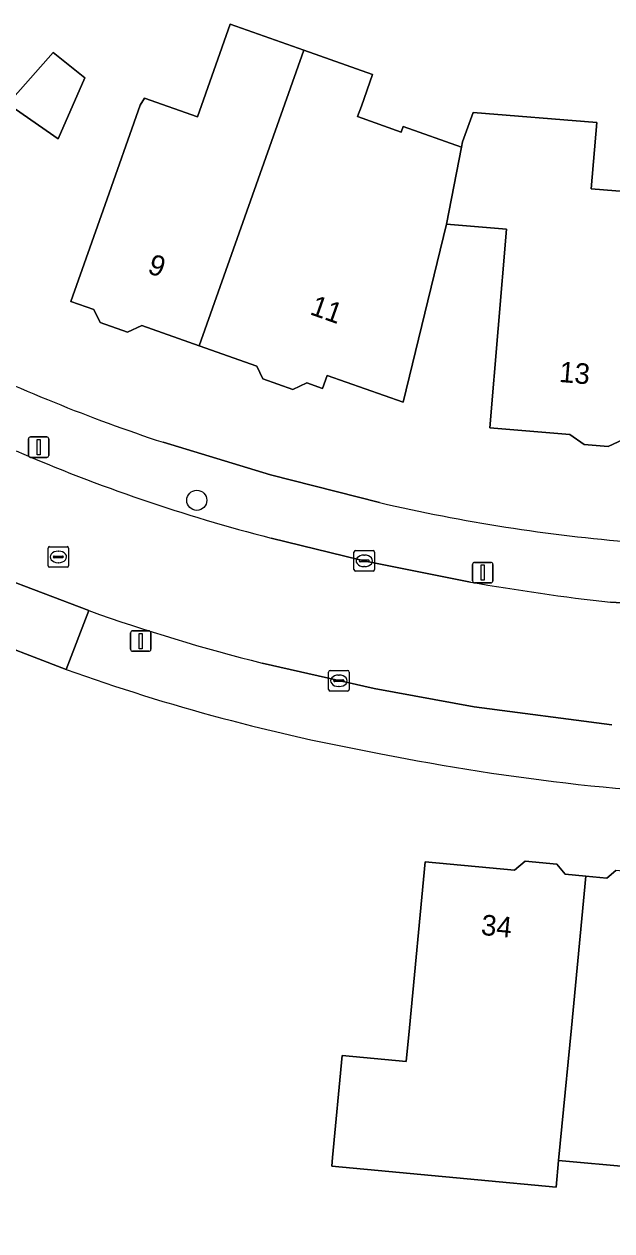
# Model space of a CAD drawing. Extents: x 161347 to 161881, y 382161 to 382804.
# Drawn here: x 161534.1 to 161562.7, y 382240.1 to 382298.9 of the extents above; entities that cross this region are included whole.
import ezdxf

# ---------------------------------------------------------------- set-up
doc = ezdxf.new("R2010")
doc.units = 0
for name, color, linetype in [('IMGEO_Boom', 7, 'Continuous'), ('IMGEO_Erf', 7, 'Continuous'), ('IMGEO_Kolk', 7, 'Continuous'), ('IMGEO_Lichtmast', 7, 'Continuous'), ('IMGEO_Pand', 7, 'Continuous'), ('IMGEO_Pand_nummerreeks', 7, 'Continuous'), ('IMGEO_Rijbaan_lokaal_open', 7, 'Continuous'), ('IMGEO_Rioolput', 7, 'Continuous'), ('IMGEO_Voetpad_open', 7, 'Continuous')]:
    doc.layers.add(name, color=color, linetype=linetype)

msp = doc.modelspace()

# ---------------------------------------------------------------- linework, layer by layer
at = {"layer": 'IMGEO_Boom'}
msp.add_circle((161542.46, 382275.697), 0.489, dxfattribs=at)
at = {"layer": 'IMGEO_Erf'}
for points in [[(161563.214, 382278.661), (161562.476, 382278.312), (161561.319, 382278.408), (161560.611, 382278.898), (161556.721, 382279.219), (161557.53, 382288.906), (161554.609, 382289.153), (161552.505, 382280.471), (161548.799, 382281.783), (161548.572, 382281.142), (161547.811, 382281.412), (161547.14, 382281.092), (161545.678, 382281.61), (161545.38, 382282.234), (161542.582, 382283.225), (161539.787, 382284.215), (161539.082, 382283.879), (161537.751, 382284.351), (161537.45, 382284.984), (161536.323, 382285.383), (161537.993, 382290.096), (161539.711, 382294.946), (161539.91, 382295.288), (161542.49, 382294.374), (161544.089, 382298.888), (161547.675, 382297.617), (161551.015, 382296.434), (161550.47, 382294.897), (161550.288, 382294.382), (161552.401, 382293.633), (161552.498, 382293.908), (161555.344, 382292.899), (161555.394, 382293.152), (161555.904, 382294.591), (161561.924, 382294.094), (161561.658, 382290.87), (161565.47, 382290.555)], [(161540.817, 382278.523), (161546.054, 382276.944), (161551.353, 382275.587)], [(161536.103, 382267.455), (161531.625, 382269.181), (161528.526, 382270.477)], [(161563.653, 382243.214), (161560.073, 382243.551), (161559.947, 382242.238), (161556.14, 382242.596), (161549.029, 382243.265), (161549.069, 382243.686), (161549.536, 382248.664), (161552.653, 382248.371), (161552.806, 382250), (161553.568, 382258.088), (161557.917, 382257.679), (161558.448, 382258.118), (161559.985, 382257.973), (161560.382, 382257.493), (161561.398, 382257.398), (161562.417, 382257.302), (161562.857, 382257.666)]]:
    msp.add_lwpolyline(points, dxfattribs=at)
msp.add_lwpolyline([(161535.705, 382293.299), (161533.261, 382295.006), (161535.469, 382297.513), (161537.017, 382296.273)], close=True, dxfattribs=at)
for centre, radius, start, end in [((161567.389, 382359.053), 84.801, 244.1027, 251.73863), ((161570.871, 382359.893), 86.536, 256.96475, 265.25243), ((161568.859, 382359.195), 97.413, 250.35082, 259.68483), ((161573.13, 382371.474), 110.276, 258.64383, 268.75651)]:
    msp.add_arc(centre, radius, start, end, dxfattribs=at)
at = {"layer": 'IMGEO_Kolk'}
for p, q in [((161550.11, 382272.324), (161550.11, 382273.176)), ((161550.185, 382273.25), (161551.037, 382273.25)), ((161551.111, 382273.176), (161551.111, 382272.324)), ((161550.369, 382272.744), (161550.369, 382272.756)), ((161550.807, 382272.707), (161550.409, 382272.707)), ((161550.412, 382272.793), (161550.81, 382272.793)), ((161550.621, 382272.47), (161550.596, 382272.47)), ((161550.598, 382273.03), (161550.623, 382273.03)), ((161550.853, 382272.756), (161550.853, 382272.744)), ((161551.037, 382272.25), (161550.185, 382272.25)), ((161548.875, 382266.482), (161548.875, 382267.334)), ((161548.95, 382267.408), (161549.802, 382267.408)), ((161549.363, 382267.188), (161549.388, 382267.188)), ((161549.876, 382267.334), (161549.876, 382266.482)), ((161549.134, 382266.902), (161549.134, 382266.914)), ((161549.572, 382266.865), (161549.174, 382266.865)), ((161549.177, 382266.951), (161549.575, 382266.951)), ((161549.386, 382266.628), (161549.361, 382266.628)), ((161549.618, 382266.914), (161549.618, 382266.902)), ((161549.802, 382266.408), (161548.95, 382266.408))]:
    msp.add_line(p, q, dxfattribs=at)
for points in [[(161550.11, 382272.324), (161550.11, 382273.176)], [(161550.185, 382273.25), (161551.037, 382273.25)], [(161551.111, 382273.176), (161551.111, 382272.324)], [(161551.037, 382272.25), (161550.185, 382272.25)], [(161548.875, 382266.482), (161548.875, 382267.334)], [(161548.95, 382267.408), (161549.802, 382267.408)], [(161549.876, 382267.334), (161549.876, 382266.482)], [(161549.802, 382266.408), (161548.95, 382266.408)]]:
    msp.add_lwpolyline(points, dxfattribs=at)
for centre, radius, start, end in [((161550.187, 382273.174), 0.0765, 91.55205, 178.44795), ((161550.187, 382273.174), 0.0765, 91.55205, 178.44795), ((161551.035, 382273.174), 0.0765, 1.55205, 88.44795), ((161551.035, 382273.174), 0.0765, 1.55205, 88.44795), ((161550.409, 382272.753), 0.0403, 85.87752, 175.75265), ((161550.406, 382272.743), 0.0366, 178.93798, 274.71019), ((161550.81, 382272.75), 0.043, 264.86636, 352.45326), ((161550.814, 382272.755), 0.0386, 1.73085, 96.63898), ((161550.187, 382272.326), 0.0765, 181.55205, 268.44795), ((161550.187, 382272.326), 0.0765, 181.55205, 268.44795), ((161551.035, 382272.326), 0.0765, 271.55205, 358.44795), ((161551.035, 382272.326), 0.0765, 271.55205, 358.44795), ((161548.952, 382267.332), 0.0765, 91.55205, 178.44795), ((161548.952, 382267.332), 0.0765, 91.55205, 178.44795), ((161549.8, 382267.332), 0.0765, 1.55205, 88.44795), ((161549.8, 382267.332), 0.0765, 1.55205, 88.44795), ((161549.174, 382266.911), 0.0403, 85.87752, 175.75265), ((161549.171, 382266.901), 0.0366, 178.93798, 274.71019), ((161549.575, 382266.908), 0.043, 264.86636, 352.45326), ((161549.579, 382266.913), 0.0386, 1.73085, 96.63898), ((161548.952, 382266.484), 0.0765, 181.55205, 268.44795), ((161548.952, 382266.484), 0.0765, 181.55205, 268.44795), ((161549.8, 382266.484), 0.0765, 271.55205, 358.44795), ((161549.8, 382266.484), 0.0765, 271.55205, 358.44795)]:
    msp.add_arc(centre, radius, start, end, dxfattribs=at)
for centre, major_axis, ratio, start_param, end_param in [((161550.597, 382272.75), (-0.387, 0.002), 0.722429, 4.712389, 7.853982), ((161550.622, 382272.75), (-0.39, 0.002), 0.717154, 1.570796, 4.712389), ((161549.362, 382266.908), (-0.387, 0.002), 0.722429, 4.712389, 7.853982), ((161549.387, 382266.908), (-0.39, 0.002), 0.717154, 1.570796, 4.712389)]:
    msp.add_ellipse(centre, major_axis=major_axis, ratio=ratio, start_param=start_param, end_param=end_param, dxfattribs=at)
at = {"layer": 'IMGEO_Lichtmast'}
for p, q in [((161534.266, 382277.885), (161534.266, 382278.685)), ((161534.266, 382278.685), (161534.266, 382277.885)), ((161534.366, 382278.785), (161535.156, 382278.785)), ((161535.156, 382278.785), (161534.366, 382278.785)), ((161535.256, 382278.685), (161535.256, 382277.885)), ((161535.256, 382277.885), (161535.256, 382278.685)), ((161535.156, 382277.785), (161534.366, 382277.785)), ((161534.366, 382277.785), (161535.156, 382277.785)), ((161555.88, 382271.776), (161555.88, 382272.576)), ((161555.88, 382272.576), (161555.88, 382271.776)), ((161555.98, 382272.676), (161556.77, 382272.676)), ((161556.77, 382272.676), (161555.98, 382272.676)), ((161556.87, 382272.576), (161556.87, 382271.776)), ((161556.87, 382271.776), (161556.87, 382272.576)), ((161556.77, 382271.676), (161555.98, 382271.676)), ((161555.98, 382271.676), (161556.77, 382271.676)), ((161539.236, 382268.443), (161539.236, 382269.243)), ((161539.236, 382269.243), (161539.236, 382268.443)), ((161539.336, 382269.343), (161540.126, 382269.343)), ((161540.126, 382269.343), (161539.336, 382269.343)), ((161540.226, 382269.243), (161540.226, 382268.443)), ((161540.226, 382268.443), (161540.226, 382269.243)), ((161540.126, 382268.343), (161539.336, 382268.343)), ((161539.336, 382268.343), (161540.126, 382268.343))]:
    msp.add_line(p, q, dxfattribs=at)
for points in [[(161534.686, 382278.66), (161534.836, 382278.66), (161534.836, 382277.91), (161534.686, 382277.91), (161534.686, 382278.66)], [(161556.3, 382272.551), (161556.45, 382272.551), (161556.45, 382271.801), (161556.3, 382271.801), (161556.3, 382272.551)], [(161539.656, 382269.218), (161539.806, 382269.218), (161539.806, 382268.468), (161539.656, 382268.468), (161539.656, 382269.218)]]:
    msp.add_lwpolyline(points, dxfattribs=at)
for centre, start, end in [((161534.366, 382278.685), 90, 180), ((161534.366, 382278.685), 90, 180), ((161535.156, 382278.685), 0, 90), ((161535.156, 382278.685), 360, 90), ((161534.366, 382277.885), 180, 270), ((161534.366, 382277.885), 180, 270), ((161535.156, 382277.885), 270, 0), ((161535.156, 382277.885), 270, 0), ((161555.98, 382272.576), 90, 180), ((161555.98, 382272.576), 90, 180), ((161556.77, 382272.576), 0, 90), ((161556.77, 382272.576), 360, 90), ((161555.98, 382271.776), 180, 270), ((161555.98, 382271.776), 180, 270), ((161556.77, 382271.776), 270, 0), ((161556.77, 382271.776), 270, 0), ((161539.336, 382269.243), 90, 180), ((161539.336, 382269.243), 90, 180), ((161540.126, 382269.243), 0, 90), ((161540.126, 382269.243), 360, 90), ((161539.336, 382268.443), 180, 270), ((161539.336, 382268.443), 180, 270), ((161540.126, 382268.443), 270, 0), ((161540.126, 382268.443), 270, 0)]:
    msp.add_arc(centre, 0.1, start, end, dxfattribs=at)
at = {"layer": 'IMGEO_Pand'}
for points in [[(161547.675, 382297.617), (161544.089, 382298.888), (161542.49, 382294.374), (161539.91, 382295.288), (161539.711, 382294.946), (161537.993, 382290.096), (161536.323, 382285.383), (161537.45, 382284.984), (161537.751, 382284.351), (161539.082, 382283.879), (161539.787, 382284.215), (161542.582, 382283.225)], [(161535.705, 382293.299), (161537.017, 382296.273), (161535.469, 382297.513), (161533.261, 382295.006)], [(161554.609, 382289.153), (161555.344, 382292.899), (161552.498, 382293.908), (161552.401, 382293.633), (161550.288, 382294.382), (161550.47, 382294.897), (161551.015, 382296.434), (161547.675, 382297.617), (161542.582, 382283.225), (161545.38, 382282.234), (161545.678, 382281.61), (161547.14, 382281.092), (161547.811, 382281.412), (161548.572, 382281.142), (161548.799, 382281.783), (161552.505, 382280.471)], [(161565.47, 382290.555), (161561.658, 382290.87), (161561.924, 382294.094), (161555.904, 382294.591), (161555.394, 382293.152), (161555.344, 382292.899), (161554.609, 382289.153), (161557.53, 382288.906), (161556.721, 382279.219), (161560.611, 382278.898), (161561.319, 382278.408), (161562.476, 382278.312), (161563.214, 382278.661), (161564.457, 382278.558)], [(161561.398, 382257.398), (161560.382, 382257.493), (161559.985, 382257.973), (161558.448, 382258.118), (161557.917, 382257.679), (161553.568, 382258.088), (161552.806, 382250), (161552.653, 382248.371), (161549.536, 382248.664), (161549.069, 382243.686), (161549.029, 382243.265), (161556.14, 382242.596), (161559.947, 382242.238), (161560.073, 382243.551), (161560.23, 382245.194), (161560.69, 382250)], [(161568.27, 382250), (161568.426, 382251.65), (161568.895, 382256.627), (161564.727, 382257.019), (161564.305, 382257.53), (161562.857, 382257.666), (161562.417, 382257.302), (161561.398, 382257.398), (161560.69, 382250), (161560.23, 382245.194), (161560.073, 382243.551), (161563.653, 382243.214), (161563.397, 382240.489), (161567.339, 382240.117), (161567.818, 382245.195)]]:
    msp.add_lwpolyline(points, close=True, dxfattribs=at)
at = {"layer": 'IMGEO_Rijbaan_lokaal_open'}
for points in [[(161555.781, 382271.717), (161550.838, 382272.695), (161550.402, 382272.793), (161546.074, 382273.855)], [(161530.104, 382273.158), (161532.749, 382272.019), (161537.201, 382270.326)], [(161571.202, 382270.362), (161568.518, 382270.387), (161562.603, 382270.731)], [(161545.644, 382267.772), (161551.101, 382266.526), (161555.961, 382265.643), (161562.662, 382264.762)]]:
    msp.add_lwpolyline(points, dxfattribs=at)
for centre, radius, start, end in [((161566.952, 382355.098), 83.882, 246.61937, 255.58801), ((161575.336, 382382.925), 112.914, 260.02676, 263.52495), ((161567.322, 382354.666), 89.557, 250.3467, 255.99227)]:
    msp.add_arc(centre, radius, start, end, dxfattribs=at)
at = {"layer": 'IMGEO_Rioolput'}
for p, q in [((161535.221, 382272.513), (161535.221, 382273.365)), ((161535.296, 382273.439), (161536.148, 382273.439)), ((161535.709, 382273.219), (161535.734, 382273.219)), ((161536.222, 382273.365), (161536.222, 382272.513)), ((161535.48, 382272.933), (161535.48, 382272.945)), ((161535.918, 382272.896), (161535.52, 382272.896)), ((161535.523, 382272.982), (161535.921, 382272.982)), ((161535.732, 382272.659), (161535.707, 382272.659)), ((161535.964, 382272.945), (161535.964, 382272.933)), ((161536.148, 382272.439), (161535.296, 382272.439))]:
    msp.add_line(p, q, dxfattribs=at)
for points in [[(161535.221, 382272.513), (161535.221, 382273.365)], [(161535.296, 382273.439), (161536.148, 382273.439)], [(161536.222, 382273.365), (161536.222, 382272.513)], [(161536.148, 382272.439), (161535.296, 382272.439)]]:
    msp.add_lwpolyline(points, dxfattribs=at)
for centre, radius, start, end in [((161535.298, 382273.363), 0.0765, 91.55205, 178.44795), ((161535.298, 382273.363), 0.0765, 91.55205, 178.44795), ((161536.146, 382273.363), 0.0765, 1.55205, 88.44795), ((161536.146, 382273.363), 0.0765, 1.55205, 88.44795), ((161535.298, 382272.515), 0.0765, 181.55205, 268.44795), ((161535.298, 382272.515), 0.0765, 181.55205, 268.44795), ((161535.52, 382272.942), 0.0403, 85.87752, 175.75265), ((161535.517, 382272.932), 0.0366, 178.93798, 274.71019), ((161535.921, 382272.939), 0.043, 264.86636, 352.45326), ((161535.925, 382272.944), 0.0386, 1.73085, 96.63898), ((161536.146, 382272.515), 0.0765, 271.55205, 358.44795), ((161536.146, 382272.515), 0.0765, 271.55205, 358.44795)]:
    msp.add_arc(centre, radius, start, end, dxfattribs=at)
for centre, major_axis, ratio, start_param, end_param in [((161535.708, 382272.939), (-0.387, 0.002), 0.722429, 4.712389, 7.853982), ((161535.733, 382272.939), (-0.39, 0.002), 0.717154, 1.570796, 4.712389)]:
    msp.add_ellipse(centre, major_axis=major_axis, ratio=ratio, start_param=start_param, end_param=end_param, dxfattribs=at)
at = {"layer": 'IMGEO_Voetpad_open'}
for points in [[(161551.353, 382275.587), (161546.054, 382276.944), (161540.817, 382278.523)], [(161546.074, 382273.855), (161550.402, 382272.793), (161550.838, 382272.695), (161555.781, 382271.717)], [(161562.603, 382270.731), (161568.518, 382270.387), (161571.202, 382270.362)], [(161537.201, 382270.326), (161536.103, 382267.455)], [(161562.662, 382264.762), (161555.961, 382265.643), (161551.101, 382266.526), (161545.644, 382267.772)]]:
    msp.add_lwpolyline(points, dxfattribs=at)
msp.add_lwpolyline([(161532.749, 382272.019), (161531.625, 382269.181), (161536.103, 382267.455), (161537.201, 382270.326)], close=True, dxfattribs=at)
for centre, radius, start, end in [((161567.389, 382359.053), 84.801, 244.1027, 251.73863), ((161566.952, 382355.098), 83.882, 246.61937, 255.58801), ((161570.871, 382359.893), 86.536, 256.96475, 265.25243), ((161575.336, 382382.925), 112.914, 260.02676, 263.52495), ((161567.322, 382354.666), 89.557, 250.3467, 255.99227), ((161568.859, 382359.195), 97.413, 250.35082, 259.68483), ((161573.13, 382371.474), 110.276, 258.64383, 268.75651)]:
    msp.add_arc(centre, radius, start, end, dxfattribs=at)

# ---------------------------------------------------------------- texts
at = {"layer": 'IMGEO_Pand_nummerreeks'}
for s, rotation, p in [('9', 340.97691, (161540.014, 382286.777)), ('11', 340.50225, (161547.919, 382284.769)), ('13', 355.18142, (161560.07, 382281.465)), ('34', 354.5569, (161556.266, 382254.535))]:
    msp.add_text(s, height=1, rotation=rotation, dxfattribs=at).set_placement(p)

doc.saveas('drawing.dxf')
